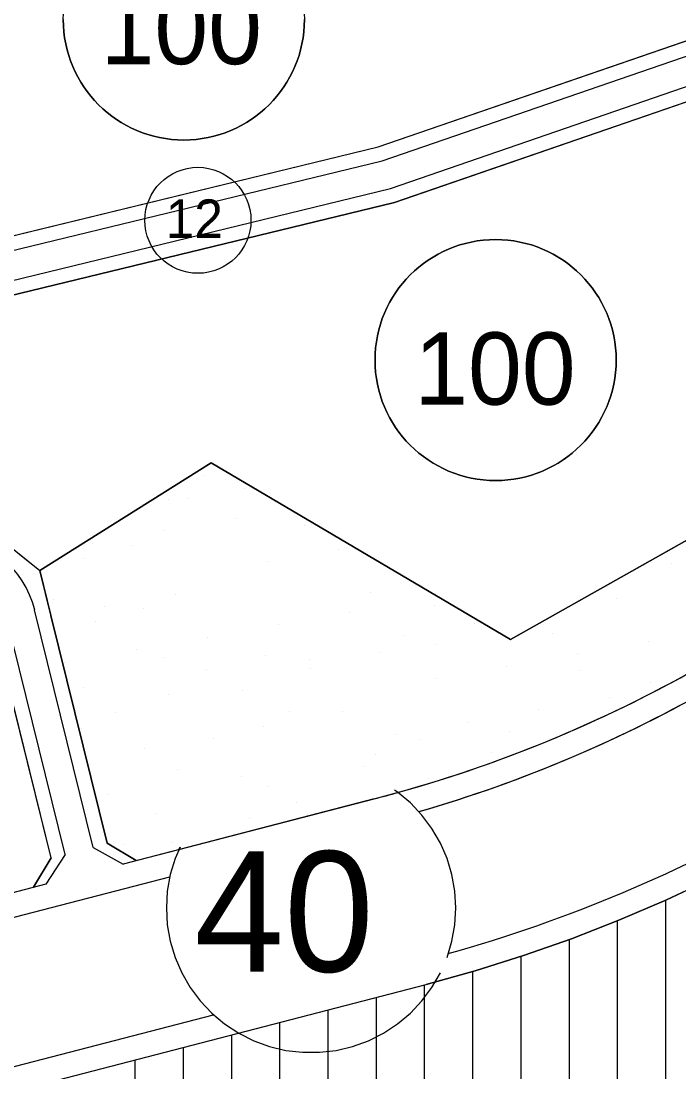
# Model space of a CAD drawing. Extents: x 427903 to 430077, y 4477233 to 4480385.
# Drawn here: x 428260.2 to 428396.6, y 4478872.5 to 4479090.6 of the extents above; entities that cross this region are included whole.
import ezdxf

# ---------------------------------------------------------------- set-up
doc = ezdxf.new("R2010")
doc.units = 0
for name, color, linetype in [('ADAKENARI', 7, 'Continuous'), ('KALDIRIM', 7, 'Continuous'), ('KALDIRIM2', 7, 'Continuous'), ('KD_DAIRE', 7, 'Continuous'), ('KD_YGEN', 7, 'Continuous'), ('PL_AYA_BOLGE_PARKI', 7, 'Continuous'), ('PL_KON_MEV_350', 7, 'Continuous'), ('PL_KON_ONE_100', 7, 'Continuous'), ('PL_KON_ONE_250', 7, 'Continuous'), ('SM_DAIRE', 7, 'Continuous'), ('SM_TAKS', 7, 'Continuous'), ('SM_YGEN', 7, 'Continuous'), ('TR_AZYOGUNKONUT', 7, 'Continuous'), ('TR_ORTAGELISME', 7, 'Continuous'), ('TR_ORTAYOGUNKONUT', 7, 'Continuous'), ('TR_PARKALANI', 7, 'Continuous')]:
    doc.layers.add(name, color=color, linetype=linetype)

msp = doc.modelspace()

# ---------------------------------------------------------------- linework, layer by layer
at = {"layer": 'ADAKENARI'}
for p, q in [((428334.22, 4479064.44), (428407.87, 4479089.86)), ((428337.6, 4479052.91), (428412.82, 4479078.87)), ((428245.6, 4479042.9), (428334.22, 4479064.44)), ((428245.8, 4479030.61), (428337.6, 4479052.91)), ((428466.09, 4479021.09), (428361.62, 4478962.24)), ((428466.09, 4479021.09), (428361.62, 4478962.24)), ((428264.07, 4478976.56), (428299.56, 4478998.87)), ((428361.62, 4478962.24), (428299.56, 4478998.87)), ((428361.62, 4478962.24), (428299.56, 4478998.87)), ((428251.89, 4478986.28), (428264.07, 4478976.56)), ((428266.36, 4478967.23), (428264.07, 4478976.56)), ((428266.39, 4478916.9), (428253.39, 4478969.73)), ((428278.01, 4478919.92), (428266.36, 4478967.22)), ((428333.4, 4478929.15), (428281.32, 4478915.62)), ((428284.04, 4478916.32), (428278.01, 4478919.92)), ((428266.39, 4478916.9), (428262.75, 4478910.79)), ((428265.28, 4478911.45), (428140.82, 4478879.11)), ((428403.36, 4478912.58), (428393.82, 4478908.1)), ((428393.82, 4478908.1), (428384.13, 4478903.94)), ((428384.13, 4478903.94), (428374.31, 4478900.1)), ((428374.31, 4478900.1), (428364.37, 4478896.6)), ((428364.37, 4478896.6), (428354.31, 4478893.44)), ((428354.31, 4478893.44), (428344.16, 4478890.62)), ((428262.06, 4478869.29), (428344.16, 4478890.62))]:
    msp.add_line(p, q, dxfattribs=at)
msp.add_arc((428263.4, 4479198.54), 278.34, 284.5655, 300.0039, dxfattribs=at)
at = {"layer": 'KALDIRIM'}
for p, q in [((427998.94, 4478837.08), (428291, 4478912.97)), ((428000.42, 4478806.47), (428300.08, 4478884.33))]:
    msp.add_line(p, q, dxfattribs=at)
for radius, start in [(277.99, 286.1161), (307.99, 285.6869)]:
    msp.add_arc((428265.44, 4479193.55), radius, start, 300.0039, dxfattribs=at)
at = {"layer": 'KALDIRIM2'}
for p, q in [((428335.06, 4479061.56), (428409.11, 4479087.11)), ((428336.75, 4479055.8), (428411.58, 4479081.62)), ((428248.93, 4479040.63), (428335.06, 4479061.56)), ((428250.35, 4479034.8), (428336.75, 4479055.8)), ((428275.13, 4478919.05), (428262.99, 4478968.36)), ((428269.3, 4478917.62), (428257.17, 4478966.93)), ((428269.3, 4478917.62), (428265.28, 4478911.45)), ((428275.13, 4478919.05), (428281.32, 4478915.62))]:
    msp.add_line(p, q, dxfattribs=at)
for centre, radius, start, end in [((428243.77, 4478963.63), 19.8, 13.8267, 88.9548), ((428265.44, 4479193.55), 277.99, 286.1333, 300.0041)]:
    msp.add_arc(centre, radius, start, end, dxfattribs=at)
at = {"layer": 'KD_DAIRE'}
for p, q in [((428338.21, 4478930.56), (428337.62, 4478930.95)), ((428340.88, 4478928.32), (428338.21, 4478930.56)), ((428340.88, 4478928.32), (428338.21, 4478930.56)), ((428343.27, 4478925.78), (428340.88, 4478928.32)), ((428343.27, 4478925.78), (428340.88, 4478928.32)), ((428345.36, 4478922.98), (428343.27, 4478925.78)), ((428345.36, 4478922.98), (428343.27, 4478925.78)), ((428347.1, 4478919.96), (428345.36, 4478922.98)), ((428347.1, 4478919.96), (428345.36, 4478922.98)), ((428348.48, 4478916.76), (428347.1, 4478919.96)), ((428348.48, 4478916.76), (428347.1, 4478919.96)), ((428293.13, 4478919.15), (428292.1, 4478916.76)), ((428293.13, 4478919.15), (428292.1, 4478916.76)), ((428292.1, 4478916.76), (428291.1, 4478913.42)), ((428292.1, 4478916.76), (428291.1, 4478913.42)), ((428349.48, 4478913.42), (428348.48, 4478916.76)), ((428349.48, 4478913.42), (428348.48, 4478916.76)), ((428291.1, 4478913.42), (428290.49, 4478909.98)), ((428291.1, 4478913.42), (428290.49, 4478909.98)), ((428350.09, 4478909.98), (428349.48, 4478913.42)), ((428350.09, 4478909.98), (428349.48, 4478913.42)), ((428290.49, 4478909.98), (428290.29, 4478906.5)), ((428290.49, 4478909.98), (428290.29, 4478906.5)), ((428350.29, 4478906.5), (428350.09, 4478909.98)), ((428350.29, 4478906.5), (428350.09, 4478909.98)), ((428290.29, 4478906.5), (428290.49, 4478903.02)), ((428290.29, 4478906.5), (428290.49, 4478903.02)), ((428350.09, 4478903.02), (428350.29, 4478906.5)), ((428350.09, 4478903.02), (428350.29, 4478906.5)), ((428350.29, 4478906.5), (428350.29, 4478906.5)), ((428350.29, 4478906.5), (428350.29, 4478906.5)), ((428290.49, 4478903.02), (428291.1, 4478899.58)), ((428290.49, 4478903.02), (428291.1, 4478899.58)), ((428349.48, 4478899.58), (428350.09, 4478903.02)), ((428349.48, 4478899.58), (428350.09, 4478903.02)), ((428291.1, 4478899.58), (428292.1, 4478896.24)), ((428291.1, 4478899.58), (428292.1, 4478896.24)), ((428348.48, 4478896.24), (428349.48, 4478899.58)), ((428348.48, 4478896.24), (428349.48, 4478899.58)), ((428292.1, 4478896.24), (428293.48, 4478893.03)), ((428292.1, 4478896.24), (428293.48, 4478893.03)), ((428293.48, 4478893.03), (428295.23, 4478890.01)), ((428293.48, 4478893.03), (428295.23, 4478890.01)), ((428345.36, 4478890.01), (428347.1, 4478893.03)), ((428345.36, 4478890.01), (428347.1, 4478893.03)), ((428295.23, 4478890.01), (428297.31, 4478887.21)), ((428295.23, 4478890.01), (428297.31, 4478887.21)), ((428343.27, 4478887.21), (428345.36, 4478890.01)), ((428343.27, 4478887.21), (428345.36, 4478890.01)), ((428297.31, 4478887.21), (428299.7, 4478884.68)), ((428297.31, 4478887.21), (428299.7, 4478884.68)), ((428340.88, 4478884.68), (428343.27, 4478887.21)), ((428340.88, 4478884.68), (428343.27, 4478887.21)), ((428299.7, 4478884.68), (428302.38, 4478882.43)), ((428299.7, 4478884.68), (428302.38, 4478882.43)), ((428338.21, 4478882.43), (428340.88, 4478884.68)), ((428338.21, 4478882.43), (428340.88, 4478884.68)), ((428302.38, 4478882.43), (428305.29, 4478880.52)), ((428302.38, 4478882.43), (428305.29, 4478880.52)), ((428335.29, 4478880.52), (428338.21, 4478882.43)), ((428335.29, 4478880.52), (428338.21, 4478882.43)), ((428305.29, 4478880.52), (428308.41, 4478878.95)), ((428305.29, 4478880.52), (428308.41, 4478878.95)), ((428332.17, 4478878.95), (428335.29, 4478880.52)), ((428332.17, 4478878.95), (428335.29, 4478880.52)), ((428308.41, 4478878.95), (428311.69, 4478877.76)), ((428308.41, 4478878.95), (428311.69, 4478877.76)), ((428328.89, 4478877.76), (428332.17, 4478878.95)), ((428328.89, 4478877.76), (428332.17, 4478878.95)), ((428311.69, 4478877.76), (428315.08, 4478876.95)), ((428311.69, 4478877.76), (428315.08, 4478876.95)), ((428315.08, 4478876.95), (428318.55, 4478876.55)), ((428315.08, 4478876.95), (428318.55, 4478876.55)), ((428318.55, 4478876.55), (428322.03, 4478876.55)), ((428318.55, 4478876.55), (428322.03, 4478876.55)), ((428322.03, 4478876.55), (428325.5, 4478876.95)), ((428322.03, 4478876.55), (428325.5, 4478876.95)), ((428325.5, 4478876.95), (428328.89, 4478877.76)), ((428325.5, 4478876.95), (428328.89, 4478877.76))]:
    msp.add_line(p, q, dxfattribs=at)
at = {"layer": 'PL_AYA_BOLGE_PARKI'}
for points in [[(428402.58, 4478957.5), (428429.74, 4478973.19), (428430.26, 4478973.49), (428430.27, 4478973.49), (428466.09, 4479021.09), (428361.62, 4478962.24), (428299.56, 4478998.87), (428264.07, 4478976.56), (428266.36, 4478967.22), (428278.01, 4478919.92), (428284.03, 4478916.32), (428284.04, 4478916.33), (428292.91, 4478918.63), (428293.13, 4478919.15), (428292.91, 4478918.63), (428333.4, 4478929.15)], [(428338.31, 4478930.47), (428338.21, 4478930.56), (428338.31, 4478930.47)]]:
    msp.add_lwpolyline(points, dxfattribs=at)
for start, end in [(285.613, 300.0039), (284.5655, 285.613)]:
    msp.add_arc((428263.4, 4479198.54), 278.34, start, end, dxfattribs=at)
at = {"layer": 'PL_KON_MEV_350'}
msp.add_lwpolyline([(427917.08, 4478776.46), (427952.24, 4478756.14), (427978.14, 4478749.76), (428034.65, 4478768.71), (428059.31, 4478768.48), (428083.94, 4478765.51), (428118.4, 4478803.55), (428180.49, 4478826.14), (428213.15, 4478841.93), (428259.26, 4478824.14), (428262.06, 4478869.29), (428344.16, 4478890.62), (428354.31, 4478893.44), (428364.37, 4478896.6), (428374.31, 4478900.1), (428384.13, 4478903.94), (428393.82, 4478908.1), (428403.36, 4478912.58)], dxfattribs=at)
at = {"layer": 'PL_KON_ONE_100'}
for points in [[(428245.6, 4479042.9), (428334.22, 4479064.44), (428407.87, 4479089.86), (428414.97, 4479093.88), (428336.42, 4479140.19), (428162.77, 4479091.94), (428162.26, 4479088.05), (428236.43, 4479044.27), (428245.6, 4479042.9)], [(428412.82, 4479078.87), (428337.6, 4479052.91), (428245.8, 4479030.61), (428161.23, 4479010.05), (428153.73, 4479002.08), (428148.66, 4478973.65), (428150.94, 4478971.76), (428192.16, 4478987.37), (428251.89, 4478986.28), (428264.07, 4478976.56), (428299.56, 4478998.87), (428361.62, 4478962.24), (428466.09, 4479021.09), (428498.91, 4479064.71), (428518.19, 4479127.46), (428510.04, 4479134), (428456.71, 4479103.76), (428412.82, 4479078.87)]]:
    msp.add_lwpolyline(points, dxfattribs=at)
at = {"layer": 'PL_KON_ONE_250'}
msp.add_lwpolyline([(428262.75, 4478910.79), (428266.39, 4478916.9), (428258.27, 4478949.89), (428142.11, 4478950.98), (428140.82, 4478879.11), (428262.75, 4478910.79), (428262.75, 4478910.79)], dxfattribs=at)
at = {"layer": 'SM_DAIRE'}
for centre, radius in [((428293.92, 4479090.87), 25), ((428296.84, 4479049.21), 11), ((428358.55, 4479020.21), 25)]:
    msp.add_circle(centre, radius, dxfattribs=at)
at = {"layer": 'TR_AZYOGUNKONUT'}
for points in [[(428162.26, 4479088.05), (428236.43, 4479044.27), (428245.6, 4479042.9), (428334.22, 4479064.44), (428407.87, 4479089.86), (428414.97, 4479093.88), (428336.42, 4479140.19), (428162.77, 4479091.94), (428162.26, 4479088.05)], [(428456.71, 4479103.76), (428412.82, 4479078.87), (428337.6, 4479052.91), (428245.8, 4479030.61), (428161.23, 4479010.05), (428153.73, 4479002.08), (428148.66, 4478973.65), (428150.94, 4478971.76), (428192.16, 4478987.37), (428251.89, 4478986.28), (428264.07, 4478976.56), (428299.56, 4478998.87), (428361.62, 4478962.24), (428466.09, 4479021.09), (428498.91, 4479064.71), (428518.19, 4479127.46), (428510.04, 4479134), (428456.71, 4479103.76)]]:
    msp.add_lwpolyline(points, dxfattribs=at)
for centre, start, end in [((428293.92, 4479090.87), 180, 0), ((428358.55, 4479020.21), 0, 180), ((428358.55, 4479020.21), 180, 0)]:
    msp.add_arc(centre, 25, start, end, dxfattribs=at)
at = {"layer": 'TR_ORTAGELISME'}
msp.add_lwpolyline([(428262.75, 4478910.79), (428266.39, 4478916.9), (428258.27, 4478949.89), (428142.11, 4478950.98), (428140.82, 4478879.11), (428262.75, 4478910.79), (428262.75, 4478910.79)], dxfattribs=at)
at = {"layer": 'TR_ORTAYOGUNKONUT'}
for p, q in [((428393.84, 4478829.27), (428393.84, 4478908.11)), ((428383.84, 4478820.47), (428383.84, 4478903.82)), ((428373.84, 4478811.67), (428373.84, 4478899.94)), ((428363.84, 4478802.88), (428363.84, 4478896.44)), ((428353.84, 4478794.08), (428353.84, 4478893.31)), ((428343.84, 4478588.63), (428343.84, 4478890.54)), ((428333.84, 4478593.65), (428333.84, 4478887.94)), ((428323.84, 4478598.99), (428323.84, 4478885.34)), ((428313.84, 4478604.34), (428313.84, 4478882.74)), ((428303.84, 4478609.69), (428303.84, 4478880.14)), ((428293.84, 4478615.04), (428293.84, 4478877.55)), ((428283.84, 4478620.39), (428283.84, 4478874.95))]:
    msp.add_line(p, q, dxfattribs=at)
at = {"layer": 'TR_PARKALANI'}
for p, q in [((428297.96, 4478996.32), (428297.96, 4478996.32)), ((428297.96, 4478996.32), (428297.96, 4478996.32)), ((428306.42, 4478993.53), (428306.42, 4478993.53)), ((428294.65, 4478991.45), (428294.65, 4478991.45)), ((428290.78, 4478991.21), (428290.78, 4478991.21)), ((428304.62, 4478987.34), (428304.62, 4478987.34)), ((428304.62, 4478987.34), (428304.62, 4478987.34)), ((428289.85, 4478984.74), (428289.85, 4478984.74)), ((428289.85, 4478984.74), (428289.85, 4478984.74)), ((428319, 4478985.77), (428319, 4478985.77)), ((428319, 4478985.77), (428319, 4478985.77)), ((428320.33, 4478986), (428320.33, 4478986)), ((428275.08, 4478982.14), (428275.08, 4478982.14)), ((428275.08, 4478982.14), (428275.08, 4478982.14)), ((428283.16, 4478981.81), (428283.16, 4478981.81)), ((428283.16, 4478981.81), (428283.16, 4478981.81)), ((428326.06, 4478980.97), (428326.06, 4478980.97)), ((428326.06, 4478980.97), (428326.06, 4478980.97)), ((428273.41, 4478979.04), (428273.41, 4478979.04)), ((428311.28, 4478978.36), (428311.28, 4478978.36)), ((428311.28, 4478978.36), (428311.28, 4478978.36)), ((428395.06, 4478977.9), (428395.06, 4478977.9)), ((428292.15, 4478971.64), (428292.15, 4478971.64)), ((428292.15, 4478971.64), (428292.15, 4478971.64)), ((428332.72, 4478971.99), (428332.72, 4478971.99)), ((428332.72, 4478971.99), (428332.72, 4478971.99)), ((428381.78, 4478973.18), (428381.78, 4478973.18)), ((428266.97, 4478970.55), (428266.97, 4478970.55)), ((428266.97, 4478970.55), (428266.97, 4478970.55)), ((428383.69, 4478970.82), (428383.69, 4478970.82)), ((428383.69, 4478970.82), (428383.69, 4478970.82)), ((428277.38, 4478969.03), (428277.38, 4478969.03)), ((428277.38, 4478969.03), (428277.38, 4478969.03)), ((428285.46, 4478968.71), (428285.46, 4478968.71)), ((428285.46, 4478968.71), (428285.46, 4478968.71)), ((428328.35, 4478967.87), (428328.35, 4478967.87)), ((428328.35, 4478967.87), (428328.35, 4478967.87)), ((428345.94, 4478969.22), (428345.94, 4478969.22)), ((428275.7, 4478965.94), (428275.7, 4478965.94)), ((428313.58, 4478965.26), (428313.58, 4478965.26)), ((428313.58, 4478965.26), (428313.58, 4478965.26)), ((428354.15, 4478965.61), (428354.15, 4478965.61)), ((428354.15, 4478965.61), (428354.15, 4478965.61)), ((428339.38, 4478963.01), (428339.38, 4478963.01)), ((428339.38, 4478963.01), (428339.38, 4478963.01)), ((428370.29, 4478963.54), (428370.29, 4478963.54)), ((428370.29, 4478963.54), (428370.29, 4478963.54)), ((428298.81, 4478962.66), (428298.81, 4478962.66)), ((428298.81, 4478962.66), (428298.81, 4478962.66)), ((428346.4, 4478961.09), (428346.4, 4478961.09)), ((428390.35, 4478961.84), (428390.35, 4478961.84)), ((428390.35, 4478961.84), (428390.35, 4478961.84)), ((428284.04, 4478960.05), (428284.04, 4478960.05)), ((428284.04, 4478960.05), (428284.04, 4478960.05)), ((428310.86, 4478958.81), (428310.86, 4478958.81)), ((428334.45, 4478959.58), (428334.45, 4478959.58)), ((428334.45, 4478959.58), (428334.45, 4478959.58)), ((428375.58, 4478959.24), (428375.58, 4478959.24)), ((428375.58, 4478959.24), (428375.58, 4478959.24)), ((428269.27, 4478957.45), (428269.27, 4478957.45)), ((428269.27, 4478957.45), (428269.27, 4478957.45)), ((428289.61, 4478958.41), (428289.61, 4478958.41)), ((428320.02, 4478958.12), (428320.02, 4478958.12)), ((428360.81, 4478956.63), (428360.81, 4478956.63)), ((428360.81, 4478956.63), (428360.81, 4478956.63)), ((428298.55, 4478955.89), (428298.55, 4478955.89)), ((428320.24, 4478956.28), (428320.24, 4478956.28)), ((428320.24, 4478956.28), (428320.24, 4478956.28)), ((428375.94, 4478955.88), (428375.94, 4478955.88)), ((428273.11, 4478952.16), (428273.11, 4478952.16)), ((428346.04, 4478954.03), (428346.04, 4478954.03)), ((428346.04, 4478954.03), (428346.04, 4478954.03)), ((428390.72, 4478953.28), (428390.72, 4478953.28)), ((428290.77, 4478950.7), (428290.77, 4478950.7)), ((428306, 4478951.68), (428306, 4478951.68)), ((428382.24, 4478950.26), (428382.24, 4478950.26)), ((428382.24, 4478950.26), (428382.24, 4478950.26)), ((428367.47, 4478947.65), (428367.47, 4478947.65)), ((428367.47, 4478947.65), (428367.47, 4478947.65)), ((428279.75, 4478947.14), (428279.75, 4478947.14)), ((428315.72, 4478947.3), (428315.72, 4478947.3)), ((428326.9, 4478947.3), (428326.9, 4478947.3)), ((428326.9, 4478947.3), (428326.9, 4478947.3)), ((428272.63, 4478943.74), (428272.63, 4478943.74)), ((428310.38, 4478944.06), (428310.38, 4478944.06)), ((428352.7, 4478945.05), (428352.7, 4478945.05)), ((428352.7, 4478945.05), (428352.7, 4478945.05)), ((428300.01, 4478941.63), (428300.01, 4478941.63)), ((428337.93, 4478942.45), (428337.93, 4478942.45)), ((428337.93, 4478942.45), (428337.93, 4478942.45)), ((428342.93, 4478941.4), (428342.93, 4478941.4)), ((428361.39, 4478943.03), (428361.39, 4478943.03)), ((428285.75, 4478939.53), (428285.75, 4478939.53)), ((428333.56, 4478938.32), (428333.56, 4478938.32)), ((428333.56, 4478938.32), (428333.56, 4478938.32)), ((428357.7, 4478938.79), (428357.7, 4478938.79)), ((428292.55, 4478935.15), (428292.55, 4478935.15)), ((428331.32, 4478935.82), (428331.32, 4478935.82)), ((428305.84, 4478933.85), (428305.84, 4478933.85)), ((428344.59, 4478933.47), (428344.59, 4478933.47)), ((428344.59, 4478933.47), (428344.59, 4478933.47)), ((428311.51, 4478931.75), (428311.51, 4478931.75)), ((428278.13, 4478930.13), (428278.13, 4478930.13)), ((428317.34, 4478928.35), (428317.34, 4478928.35)), ((428288.18, 4478926.08), (428288.18, 4478926.08)), ((428307.62, 4478925.11), (428307.62, 4478925.11)), ((428281.54, 4478919.6), (428281.54, 4478919.6)), ((428291.26, 4478920.08), (428291.26, 4478920.08))]:
    msp.add_line(p, q, dxfattribs=at)

# ---------------------------------------------------------------- texts
at = {"layer": 'KD_YGEN'}
msp.add_text('40', height=25, dxfattribs=at).set_placement((428296.12, 4478893.27))
msp.add_text('40', height=25, dxfattribs=at).set_placement((428296.12, 4478893.27))
at = {"layer": 'SM_TAKS'}
for p in [(428276.65, 4479081.61), (428341.68, 4479010.95)]:
    msp.add_text('100', height=15, dxfattribs=at).set_placement(p)
at = {"layer": 'SM_YGEN'}
msp.add_text('12', height=8, rotation=0.0002, dxfattribs=at).set_placement((428290.13, 4479045.55))

doc.saveas('drawing.dxf')
